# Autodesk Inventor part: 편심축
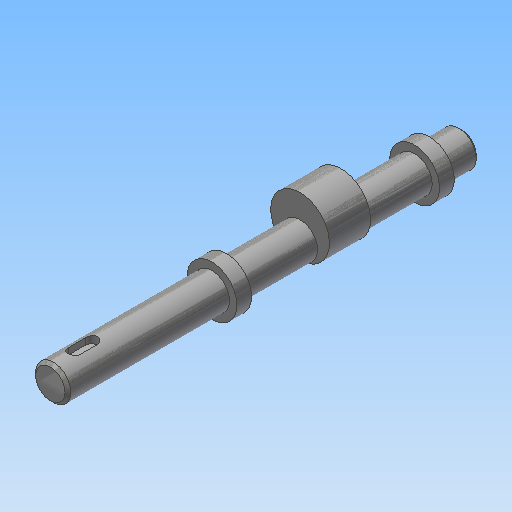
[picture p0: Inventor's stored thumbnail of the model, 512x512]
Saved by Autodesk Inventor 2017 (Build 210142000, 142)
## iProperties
Created: 2016-02
Part Number: 편심축
Material: 강철, 연강
Document SubType Name: Modeling
Designer: mduedu
Density: 1 g/cm^3
Appearance: 강철
Author: mduedu
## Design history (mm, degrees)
sketch "스케치1"
  geometry: C1 r 6 at (0, 0); 1 further point
  constraints: 1 centre point, 1 coincident
  dimensions: "d0" = 12 diameter of C1
extrude "돌출1" new body sketch "스케치1" distance "d1" = 140; taper "d2" = 0 deg
chamfer "모따기1" distance "d3" = 1; stored, may be unused: second distance "d4" = 2, angle "d5" = 45 deg
node "작업 평면1"
sketch "스케치2"
  geometry: C1 r 10 at (0, 4); C2 r 6 at (0, 0) reference; 1 further point
  constraints: 1 centre point, 1 tangent, 1 vertical alignment
  dimensions: "d7" = 20 diameter of C1
extrude "돌출2" join sketch "스케치2" stored distance "d8" = 14; taper "d9" = 0 deg
node "작업 평면2"
sketch "스케치3"
  geometry: C1 r 8.5 at (0, 0); 1 further point
  constraints: 1 centre point, 1 coincident
  dimensions: "d12" = 17 diameter of C1
extrude "돌출3" join sketch "스케치3" distance "d13" = 5; taper "d14" = 0 deg
node "작업 평면3"
sketch "스케치4"
  geometry: L1 (-5, 140)-(5, 140) reference; L2 (0, 140)-(0, 0); L3 (-2, 132)-(-2, 126); L4 (2, 126)-(2, 132); A1 r 2 centre (0, 132) between (2, 132) and (-2, 132); A2 r 2 centre (0, 126) between (-2, 126) and (2, 126)
  constraints: 6 end point, 4 point on circle, 4 tangent, 2 centre point, 2 point on line, 1 midpoint, 1 parallel, 1 perpendicular
  dimensions: "d15" = 4 distance between parallel lines of L3 L4; "d17" = 6 distance edge to line of A1 L1; "d18" = 10 dimension on A2 A1
extrude "돌출4" cut sketch "스케치4" distance "d19" = 2.5; taper "d20" = 0 deg
sketch "스케치5"
  geometry: L1 (6, 55)-(6, 139) reference; L2 (-6, 55)-(-6, 139) reference; L3 (6, 115)-(-6, 115); L4 (-5, 140)-(5, 140) reference; L5 (6, 116.5)-(4.5, 115); L6 (6, 116.5)-(6, 115); L7 (4.5, 115)-(6, 115); 1 further point
  constraints: 8 end point, 4 point on line, 2 collinear, 1 perpendicular
  dimensions: "d21" = 25 distance between parallel lines of L3 L4; "d22" = 3 diameter of L5.start L3; "d24" = 45 deg angle of L3 L5
revolve "회전1" sketch "스케치5" stored, may be unused: angle "d25" = 90 deg
sketch "스케치6"
  geometry: L1 (6, 116.5)-(4.5, 115) reference; L2 (6, 113.5)-(4.5, 115) reference; 2 further points
  constraints: 1 coincident
node "작업 평면4"
sketch "스케치7"
  geometry: C1 r 8.5 at (0, -4); 1 further point
  constraints: 1 centre point, 1 coincident
  dimensions: "d27" = 17 diameter of C1
extrude "돌출5" join sketch "스케치7" distance "d29" = 5; taper "d30" = 0 deg
node "작업점1"
node "솔리드1"
other parameters: "d6" = -48, "d11" = -11
